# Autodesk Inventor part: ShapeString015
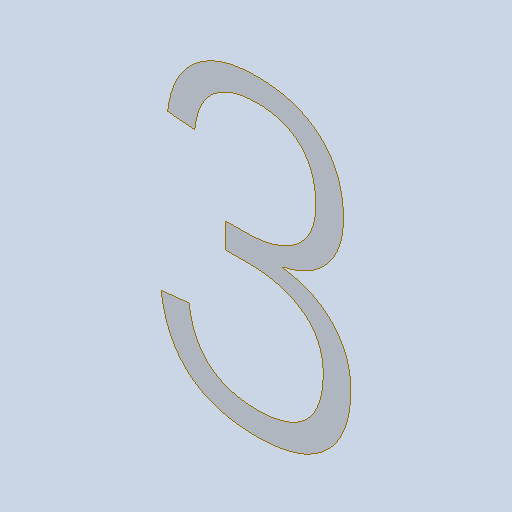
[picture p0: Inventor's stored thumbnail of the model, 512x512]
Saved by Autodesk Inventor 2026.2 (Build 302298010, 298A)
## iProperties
Created: 2026-10
Part Number: ShapeString015
Material: Générique
Document SubType Name: Modeling
Designer: mel
Density: 1 g/cm^3
Appearance: Par défaut
Author: mel
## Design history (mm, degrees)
feature "Composite1"
body "Srf1"
